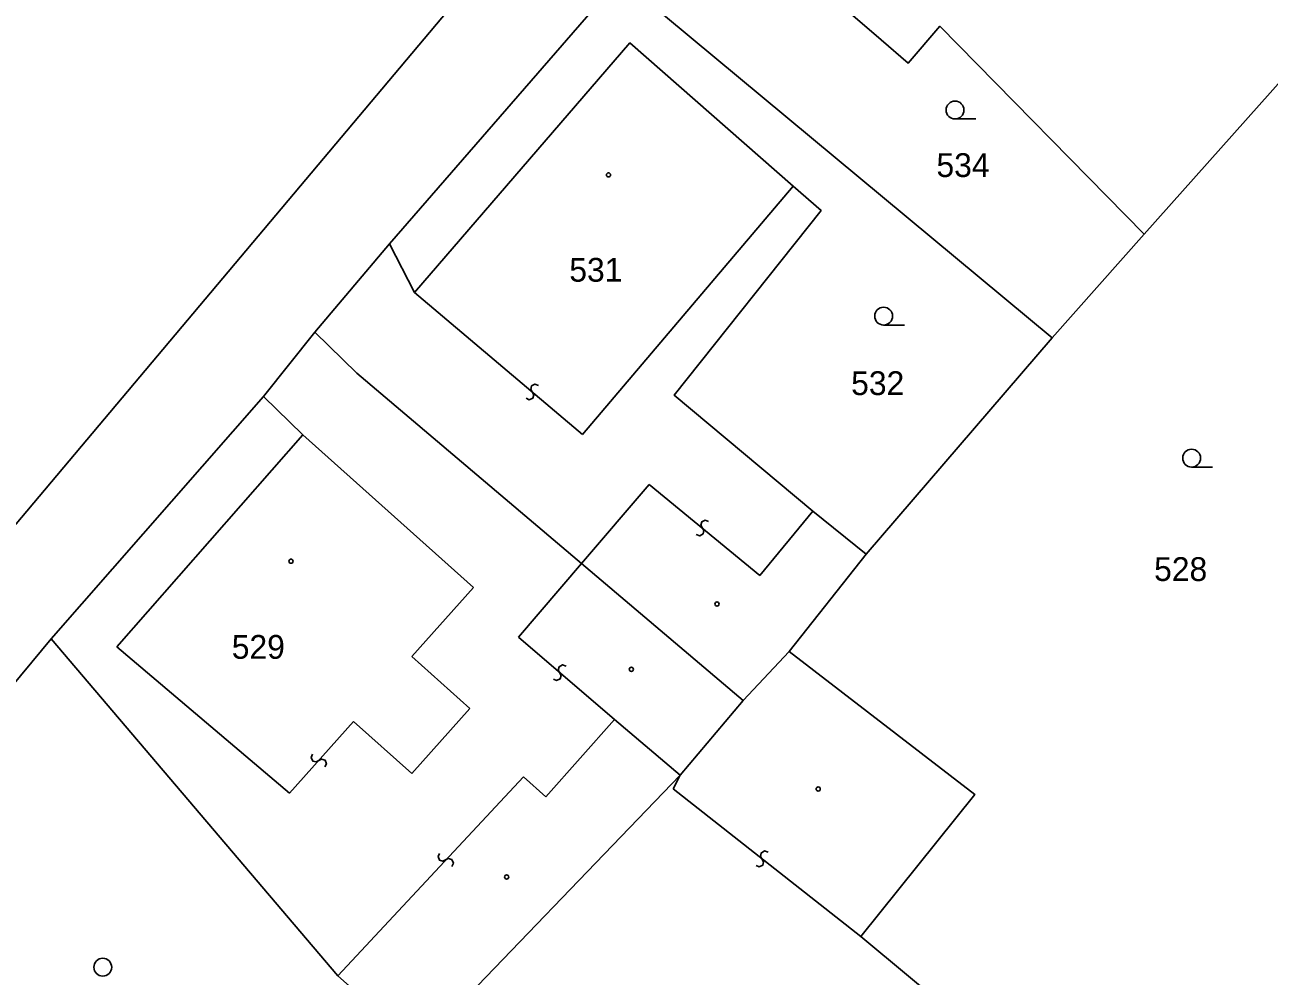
# Model space of a CAD drawing. Extents: x -748509 to -748117, y -967868 to -967533.
# Drawn here: x -748213.7 to -748161.4, y -967744.6 to -967704.6 of the extents above; entities that cross this region are included whole.
import ezdxf

# ---------------------------------------------------------------- set-up
doc = ezdxf.new("R2010")
doc.units = 0
doc.layers.add('KM', color=7, linetype='Continuous')
doc.layers.add('Vnitřní kresba', color=7, linetype='Continuous')

msp = doc.modelspace()

# ---------------------------------------------------------------- linework, layer by layer
at = {"layer": 'KM'}
for p, q in [((-748188.68, -967702.64), (-748198.36, -967713.79)), ((-748170.53, -967717.74), (-748188.68, -967702.64)), ((-748214.57, -967726.18), (-748195.27, -967703.22)), ((-748157.48, -967703.06), (-748166.66, -967713.38)), ((-748174.606, -967708.54), (-748173.731, -967708.54)), ((-748198.36, -967713.79), (-748201.5, -967717.5)), ((-748166.66, -967713.38), (-748170.53, -967717.74)), ((-748177.606, -967717.2), (-748176.731, -967717.2)), ((-748170.53, -967717.74), (-748178.34, -967726.83)), ((-748164.667, -967723.17), (-748163.792, -967723.17)), ((-748178.34, -967726.83), (-748181.57, -967730.93)), ((-748181.57, -967730.93), (-748183.5, -967732.99))]:
    msp.add_line(p, q, dxfattribs=at)
for points in [[(-748185.29, -967698.7), (-748177.71, -967705.22), (-748176.58, -967706.2), (-748175.24, -967704.64), (-748166.66, -967713.38)], [(-748178.34, -967726.83), (-748180.58, -967725.03), (-748186.4, -967720.15), (-748180.23, -967712.39), (-748181.4, -967711.37), (-748188.26, -967705.34), (-748197.31, -967715.83), (-748198.36, -967713.79)], [(-748201.5, -967717.5), (-748203.65, -967720.2), (-748212.57, -967730.39)], [(-748183.5, -967732.99), (-748190.3, -967727.22), (-748199.73, -967719.22), (-748201.5, -967717.5)], [(-748212.57, -967730.39), (-748221.81, -967741.523)], [(-748212.57, -967730.39), (-748200.54, -967744.55), (-748197.15, -967747.55)], [(-748172.55, -967747.9), (-748178.56, -967742.91), (-748173.77, -967736.94), (-748181.57, -967730.93)], [(-748183.5, -967732.99), (-748186.15, -967736.12), (-748197.15, -967747.55)]]:
    msp.add_lwpolyline(points, dxfattribs=at)
for centre, radius in [((-748174.606, -967708.165), 0.375), ((-748189.163, -967710.89), 0.0875), ((-748177.606, -967716.825), 0.375), ((-748164.666, -967722.795), 0.375), ((-748202.503, -967727.13), 0.0875), ((-748184.603, -967728.93), 0.0875), ((-748188.203, -967731.67), 0.0875), ((-748180.353, -967736.7), 0.0875), ((-748193.443, -967740.4), 0.0875), ((-748210.409, -967744.194), 0.375)]:
    msp.add_circle(centre, radius, dxfattribs=at)
at = {"layer": 'Vnitřní kresba'}
for p, q in [((-748190.25, -967721.8), (-748181.4, -967711.37)), ((-748197.31, -967715.83), (-748190.25, -967721.8)), ((-748203.65, -967720.2), (-748202, -967721.82)), ((-748209.82, -967730.73), (-748202, -967721.82)), ((-748202, -967721.82), (-748194.83, -967728.23)), ((-748190.3, -967727.22), (-748187.45, -967723.9)), ((-748187.45, -967723.9), (-748182.8, -967727.73)), ((-748182.8, -967727.73), (-748180.58, -967725.03)), ((-748190.3, -967727.22), (-748192.95, -967730.32)), ((-748194.83, -967728.23), (-748197.43, -967731.13)), ((-748192.95, -967730.32), (-748188.91, -967733.78)), ((-748202.57, -967736.88), (-748209.82, -967730.73)), ((-748197.43, -967731.13), (-748194.99, -967733.32)), ((-748194.99, -967733.32), (-748197.43, -967736.05)), ((-748199.87, -967733.87), (-748202.57, -967736.88)), ((-748197.43, -967736.05), (-748199.87, -967733.87)), ((-748188.91, -967733.78), (-748191.8, -967737.03)), ((-748188.91, -967733.78), (-748186.15, -967736.12)), ((-748192.74, -967736.19), (-748200.54, -967744.55)), ((-748191.8, -967737.03), (-748192.74, -967736.19)), ((-748186.15, -967736.12), (-748186.45, -967736.7)), ((-748186.45, -967736.7), (-748178.56, -967742.91))]:
    msp.add_line(p, q, dxfattribs=at)
for points in [[(-748192.105, -967719.741), (-748192.252, -967719.682), (-748192.397, -967719.762), (-748192.431, -967719.91), (-748192.303, -967720.13), (-748192.347, -967720.276), (-748192.494, -967720.341), (-748192.627, -967720.281)], [(-748185.48, -967726.009), (-748185.332, -967726.065), (-748185.187, -967725.984), (-748185.155, -967725.835), (-748185.287, -967725.617), (-748185.244, -967725.471), (-748185.098, -967725.403), (-748184.964, -967725.461)], [(-748190.947, -967731.542), (-748191.094, -967731.483), (-748191.24, -967731.562), (-748191.275, -967731.71), (-748191.148, -967731.93), (-748191.193, -967732.076), (-748191.341, -967732.14), (-748191.473, -967732.08)], [(-748201.598, -967735.236), (-748201.661, -967735.381), (-748201.586, -967735.529), (-748201.439, -967735.567), (-748201.215, -967735.445), (-748201.071, -967735.494), (-748201.01, -967735.643), (-748201.074, -967735.774)], [(-748195.745, -967739.96), (-748195.679, -967739.816), (-748195.751, -967739.667), (-748195.898, -967739.626), (-748196.124, -967739.743), (-748196.267, -967739.692), (-748196.325, -967739.542), (-748196.259, -967739.412)], [(-748182.46, -967739.363), (-748182.609, -967739.309), (-748182.752, -967739.394), (-748182.781, -967739.543), (-748182.645, -967739.759), (-748182.684, -967739.906), (-748182.829, -967739.976), (-748182.964, -967739.921)]]:
    msp.add_lwpolyline(points, dxfattribs=at)

# ---------------------------------------------------------------- texts
at = {"layer": 'KM'}
for s, p in [('534', (-748175.386, -967710.98)), ('531', (-748190.81, -967715.38)), ('532', (-748178.969, -967720.145)), ('528', (-748166.242, -967727.96)), ('529', (-748204.99, -967731.23))]:
    msp.add_text(s, height=1, dxfattribs=at).set_placement(p)

doc.saveas('drawing.dxf')
